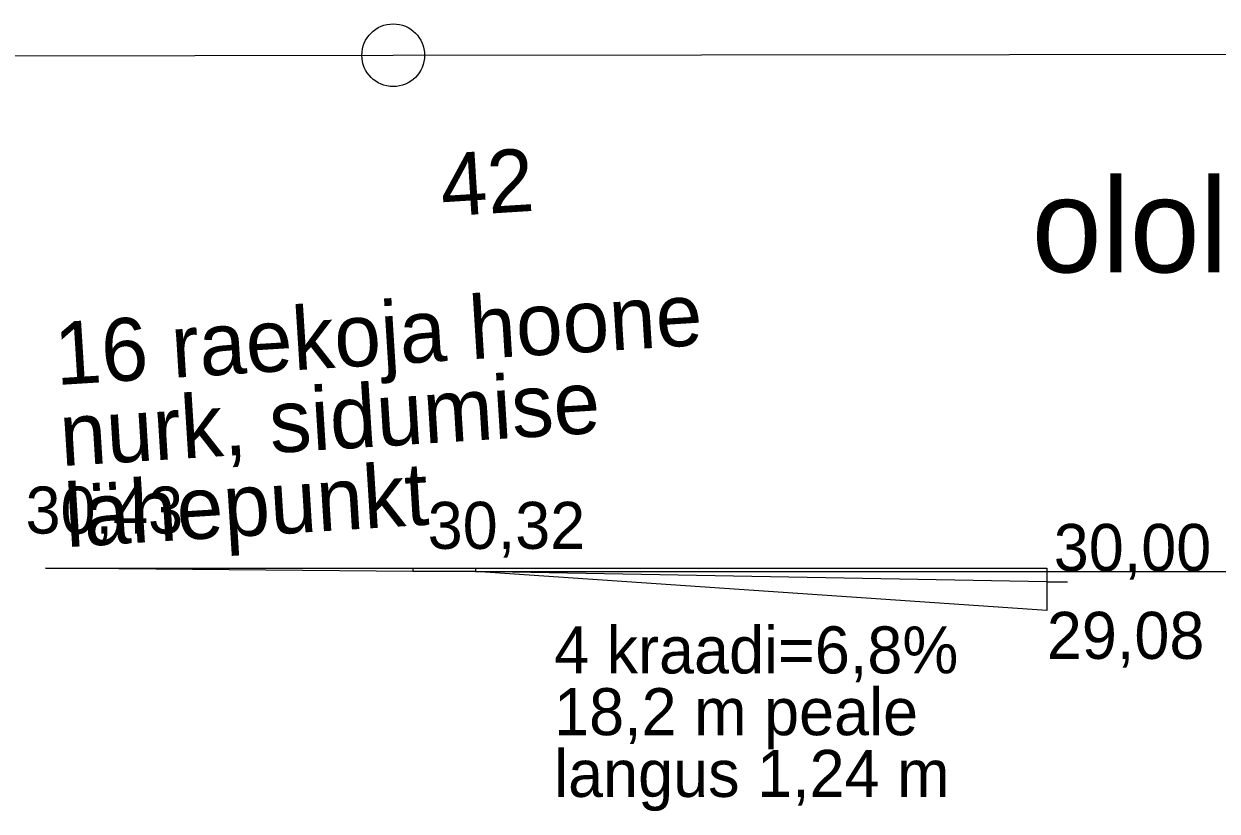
# Model space of a CAD drawing. Extents: x 738423 to 738903, y 6589762 to 6590172.
# Drawn here: x 738524.9 to 738562.92, y 6589850.71 to 6589875.8 of the extents above; entities that cross this region are included whole.
import ezdxf

# ---------------------------------------------------------------- set-up
doc = ezdxf.new("R2010")
doc.units = 0
for name, color, linetype in [('_1927_koordin_punktid_nr', 7, 'Continuous'), ('_1927_krundi_piir', 7, 'Continuous'), ('_a_olol_maapind', 7, 'Continuous'), ('a_', 7, 'Continuous')]:
    doc.layers.add(name, color=color, linetype=linetype)

msp = doc.modelspace()

# ---------------------------------------------------------------- linework, layer by layer
at = {"layer": '_1927_koordin_punktid_nr'}
msp.add_circle((738536.672, 6589874.8), 1, dxfattribs=at)
at = {"layer": '_1927_krundi_piir'}
msp.add_lwpolyline([(738456.372, 6589873.59), (738496.357, 6589874.746), (738517.697, 6589874.771), (738536.672, 6589874.8), (738566.126, 6589874.839), (738579.13, 6589874.857)], dxfattribs=at)
at = {"layer": 'a_'}
for p, q in [((738525.589, 6589858.45), (738557.499, 6589858.45)), ((738557.499, 6589857.1), (738539.292, 6589858.34)), ((738539.292, 6589858.34), (738565.682, 6589858.34)), ((738557.499, 6589858.45), (738557.499, 6589857.1))]:
    msp.add_line(p, q, dxfattribs=at)
for points in [[(738525.589, 6589858.45), (738537.292, 6589858.45), (738537.292, 6589858.34)], [(738557.499, 6589858.02), (738539.292, 6589858.34), (738537.292, 6589858.34), (738525.589, 6589858.45)], [(738537.292, 6589858.45), (738539.292, 6589858.45), (738539.292, 6589858.34)], [(738557.499, 6589858.45), (738557.499, 6589858.02), (738558.156, 6589858.02)]]:
    msp.add_lwpolyline(points, dxfattribs=at)

# ---------------------------------------------------------------- texts
at = {"layer": '_1927_koordin_punktid_nr'}
for s, p in [('42', (738538.235, 6589869.659)), ('16 raekoja hoone ', (738525.942, 6589864.286)), ('nurk, sidumise ', (738526.103, 6589861.702)), ('lähepunkt', (738526.264, 6589859.119))]:
    msp.add_text(s, height=2, rotation=3.5609, dxfattribs=at).set_placement(p)
at = {"layer": '_a_olol_maapind'}
msp.add_text('olol kõnnitee', height=3, dxfattribs=at).set_placement((738557.015, 6589867.88))
at = {"layer": 'a_'}
for s, p in [('30,43', (738524.957, 6589859.553)), ('30,32', (738537.769, 6589859.066)), ('30,00', (738557.716, 6589858.361)), ('29,08', (738557.496, 6589855.56)), ('4 kraadi=6,8%', (738541.797, 6589855.096)), ('18,2 m peale ', (738541.797, 6589853.128)), ('langus 1,24 m', (738541.797, 6589851.16))]:
    msp.add_text(s, height=1.5, dxfattribs=at).set_placement(p)

doc.saveas('drawing.dxf')
